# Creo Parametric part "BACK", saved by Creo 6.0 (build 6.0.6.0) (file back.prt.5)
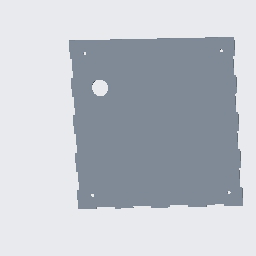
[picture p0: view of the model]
Units: Inch lbm Second (Pro/E Default); INCH, POUND, SECS

Created from: INLBS_PART_SOLID.PRT

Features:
  1. datum plane "RIGHT"
  2. datum plane "TOP"
  3. datum plane "FRONT"
  4. coordinate system
  5. sketch "Sketch 1"
  6. extrusion "Extrude 1"
  7. sketch "Sketch 3"
  8. sketch "Sketch 4"
  9. extruded cut "Extrude 3"
  10. sketch "Sketch 5"
  11. extruded cut "Extrude 4"

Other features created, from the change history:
  extruded cut "Extrude 2"
  sketch "Sketch 4"
  extruded cut "Extrude 3"

Surfaces: 54 plane, 5 cylinder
